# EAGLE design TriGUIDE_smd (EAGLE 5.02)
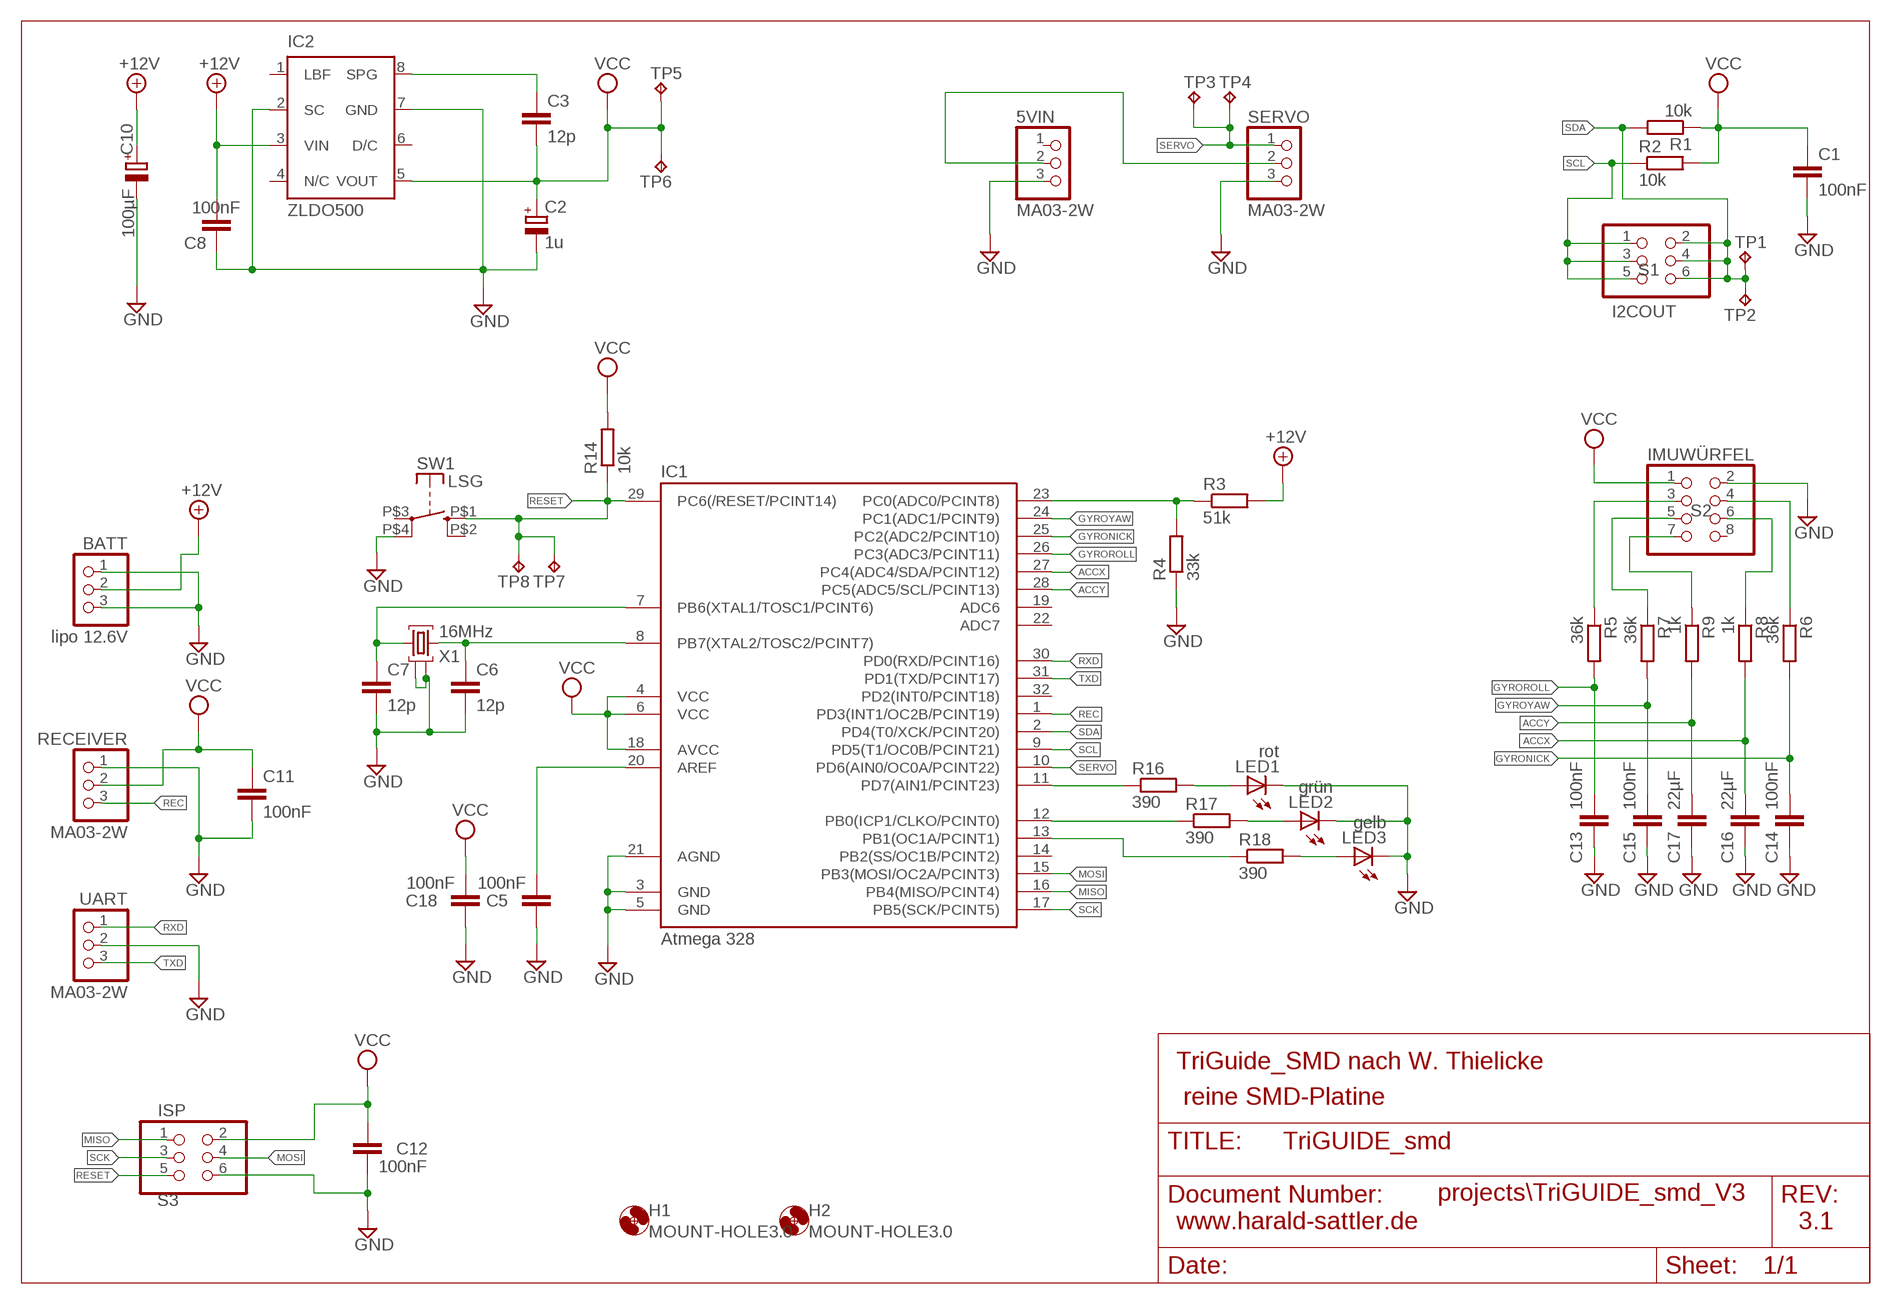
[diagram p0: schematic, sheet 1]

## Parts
5VIN  MA03-2W  PINHD-1X3_2.54-SMD  [1X03SMD]
BATT  lipo 12.6V  PINHD-1X3_2.54-SMD  [1X03SMD]
C1  100nF  C-EUC1206  [C1206]
C2  1u  CPOL-EUSMCB  [SMC_B]
C3  12p  C-EUC1206  [C1206]
C5  100nF  C-EUC1206  [C1206]
C6  12p  C-EUC1206  [C1206]
C7  12p  C-EUC1206  [C1206]
C8  100nF  C-EUC1206  [C1206]
C10  100µF  CPOL-EUD/7343-31W  [D/7343-31W]
C11  100nF  C-EUC1206  [C1206]
C12  100nF  C-EUC1206  [C1206]
C13  100nF  C-EUC1206  [C1206]
C14  100nF  C-EUC1206  [C1206]
C15  100nF  C-EUC1206  [C1206]
C16  22µF  C-EUC1206  [C1206]
C17  22µF  C-EUC1206  [C1206]
C18  100nF  C-EUC1206  [C1206]
H1  MOUNT-HOLE3.0  [3,0]
H2  MOUNT-HOLE3.0  [3,0]
I2COUT  S1  PINHD-2X3_2.54-SMD  [2X03SMD]
IC1  Atmega 328  MEGA48/88/168-AU  [TQFP32-08]
IC2  ZLDO500  [SM8]
IMUWÜRFEL  S2  PINHD-2X4_2.54-SMD  [2X04SMD]
ISP  S3  PINHD-2X3_2.54-SMD  [2X03SMD]
LED1  rot  LEDCHIPLED_1206  [CHIPLED_1206]
LED2  grün  LEDCHIPLED_1206  [CHIPLED_1206]
LED3  gelb  LEDCHIPLED_1206  [CHIPLED_1206]
R1  10k  R-EU_R1206  [R1206]
R2  10k  R-EU_R1206  [R1206]
R3  51k  R-EU_R1206  [R1206]
R4  33k  R-EU_R1206  [R1206]
R5  36k  R-EU_R1206  [R1206]
R6  36k  R-EU_R1206  [R1206]
R7  36k  R-EU_R1206  [R1206]
R8  1k  R-EU_R1206  [R1206]
R9  1k  R-EU_R1206  [R1206]
R14  10k  R-EU_R1206  [R1206]
R16  390  R-EU_R1206  [R1206]
R17  390  R-EU_R1206  [R1206]
R18  390  R-EU_R1206  [R1206]
RECEIVER  MA03-2W  PINHD-1X3_2.54-SMD  [1X03SMD]
SERVO  MA03-2W  PINHD-1X3_2.54-SMD  [1X03SMD]
SW1  LSG  [LSG]
TP1  TPB1,27  [B1,27]
TP2  TPB1,27  [B1,27]
TP3  TPB1,27  [B1,27]
TP4  TPB1,27  [B1,27]
TP5  TPB1,27  [B1,27]
TP6  TPB1,27  [B1,27]
TP7  TPB1,27  [B1,27]
TP8  TPB1,27  [B1,27]
UART  MA03-2W  PINHD-1X3_2.54-SMD  [1X03SMD]
X1  16MHz  X22  [X22]

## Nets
+12V: BATT.2 C8.2 C10.+ IC2.3(VIN) R3.2
ACCX: C16.1 IC1.27(PC4(ADC4/SDA/PCINT12)) R8.2
ACCY: C17.2 IC1.28(PC5(ADC5/SCL/PCINT13)) R9.2
AREF: C5.2 IC1.20(AREF)
GND: 5VIN.3 BATT.1 BATT.3 C1.2 C2.- C5.1 C6.2 C7.2 C8.1 C10.- C11.2 C12.2 C13.2 C14.1 C15.1 C16.2 C17.1 C18.1 IC1.3(GND) IC1.5(GND) IC1.21(AGND) IC2.2(SC) IC2.7(GND) IMUWÜRFEL.2 ISP.6 LED1.C LED2.C LED3.C R4.1 RECEIVER.1 SERVO.3 SW1.P$4(P) UART.2 X1.P$2 X1.P$4
GYRONICK: C14.2 IC1.25(PC2(ADC2/PCINT10)) R6.2
GYROROLL: C13.1 IC1.26(PC3(ADC3/PCINT11)) R5.2
GYROYAW: C15.2 IC1.24(PC1(ADC1/PCINT9)) R7.2
LED1: IC1.11(PD7(AIN1/PCINT23)) R16.1
LED2: IC1.12(PB0(ICP1/CLKO/PCINT0)) R17.1
LED3: IC1.13(PB1(OC1A/PCINT1)) R18.1
MISO: IC1.16(PB4(MISO/PCINT4)) ISP.1
MOSI: IC1.15(PB3(MOSI/OC2A/PCINT3)) ISP.4
N$1: C3.1 IC2.8(SPG)
N$4: 5VIN.2 SERVO.2
N$5: IMUWÜRFEL.3 R5.1
N$8: LED1.A R16.2
N$9: LED2.A R17.2
N$10: LED3.A R18.2
N$14: IC1.23(PC0(ADC0/PCINT8)) R3.1 R4.2
N$16: IMUWÜRFEL.4 R6.1
N$18: IMUWÜRFEL.5 R7.1
N$19: IMUWÜRFEL.6 R8.1
N$20: IMUWÜRFEL.7 R9.1
REC: IC1.1(PD3(INT1/OC2B/PCINT19)) RECEIVER.3
RESET: IC1.29(PC6(/RESET/PCINT14)) ISP.5 R14.1 SW1.P$1(S) TP7.PP(TP) TP8.PP(TP)
RXD: IC1.30(PD0(RXD/PCINT16)) UART.1
SCK: IC1.17(PB5(SCK/PCINT5)) ISP.3
SCL: I2COUT.1 I2COUT.3 I2COUT.5 IC1.9(PD5(T1/OC0B/PCINT21)) R2.1
SDA: I2COUT.2 I2COUT.4 I2COUT.6 IC1.2(PD4(T0/XCK/PCINT20)) R1.2 TP1.PP(TP) TP2.PP(TP)
SERVO: IC1.10(PD6(AIN0/OC0A/PCINT22)) SERVO.1 TP3.PP(TP) TP4.PP(TP)
TXD: IC1.31(PD1(TXD/PCINT17)) UART.3
VCC: C1.1 C2.+ C3.2 C11.1 C12.1 C18.2 IC1.4(VCC) IC1.6(VCC) IC1.18(AVCC) IC2.5(VOUT) IMUWÜRFEL.1 ISP.2 R1.1 R2.2 R14.2 RECEIVER.2 TP5.PP(TP) TP6.PP(TP)
XTAL1: C7.1 IC1.7(PB6(XTAL1/TOSC1/PCINT6)) X1.P$1
XTAL2: C6.1 IC1.8(PB7(XTAL2/TOSC2/PCINT7)) X1.P$3
Unconnected: 5VIN.1 IC1.14(PB2(SS/OC1B/PCINT2)) IC1.19(ADC6) IC1.22(ADC7) IC1.32(PD2(INT0/PCINT18)) IC2.1(LBF) IC2.4(N/C) IC2.6(D/C) IMUWÜRFEL.8 SW1.P$2(S) SW1.P$3(P)

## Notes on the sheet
- TriGuide_SMD nach W. Thielicke
- reine SMD-Platine
- projects\\TriGUIDE_smd_V3
- www.harald-sattler.de | 3.1

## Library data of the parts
5VIN BATT RECEIVER SERVO UART = pinhead:PINHD-1X3: PIN HEADER
C1 C3 C5-C8 C11-C18 = rcl:C-EU: CAPACITOR, European symbol
C2 C10 = rcl:CPOL-EU: POLARIZED CAPACITOR, European symbol
H1 H2 = holes:MOUNT-HOLE: MOUNTING HOLE with drill center marker
I2COUT ISP = pinhead:PINHD-2X3: PIN HEADER
IC1 = avr-4:MEGA48/88/168
IC2 = zetex:ZLDO500
IMUWÜRFEL = pinhead:PINHD-2X4: PIN HEADER
LED1-LED3 = led:LED: LED
R1-R9 R14 = resistor:R-EU_: RESISTOR, European symbol
R16-R18 = rcl:R-EU_: RESISTOR, European symbol
SW1 = Schurter:LSG
TP1-TP8 = testpad:TP: Test pad
X1 = crystal:X22: Reichelt SMD Keramik Quarz EUROQUARTZ X22, Standard SMD-Quarz Keramikgehäuse 2x2,5x0,6mm Grundton-Modus Lastkapazität: 12pF

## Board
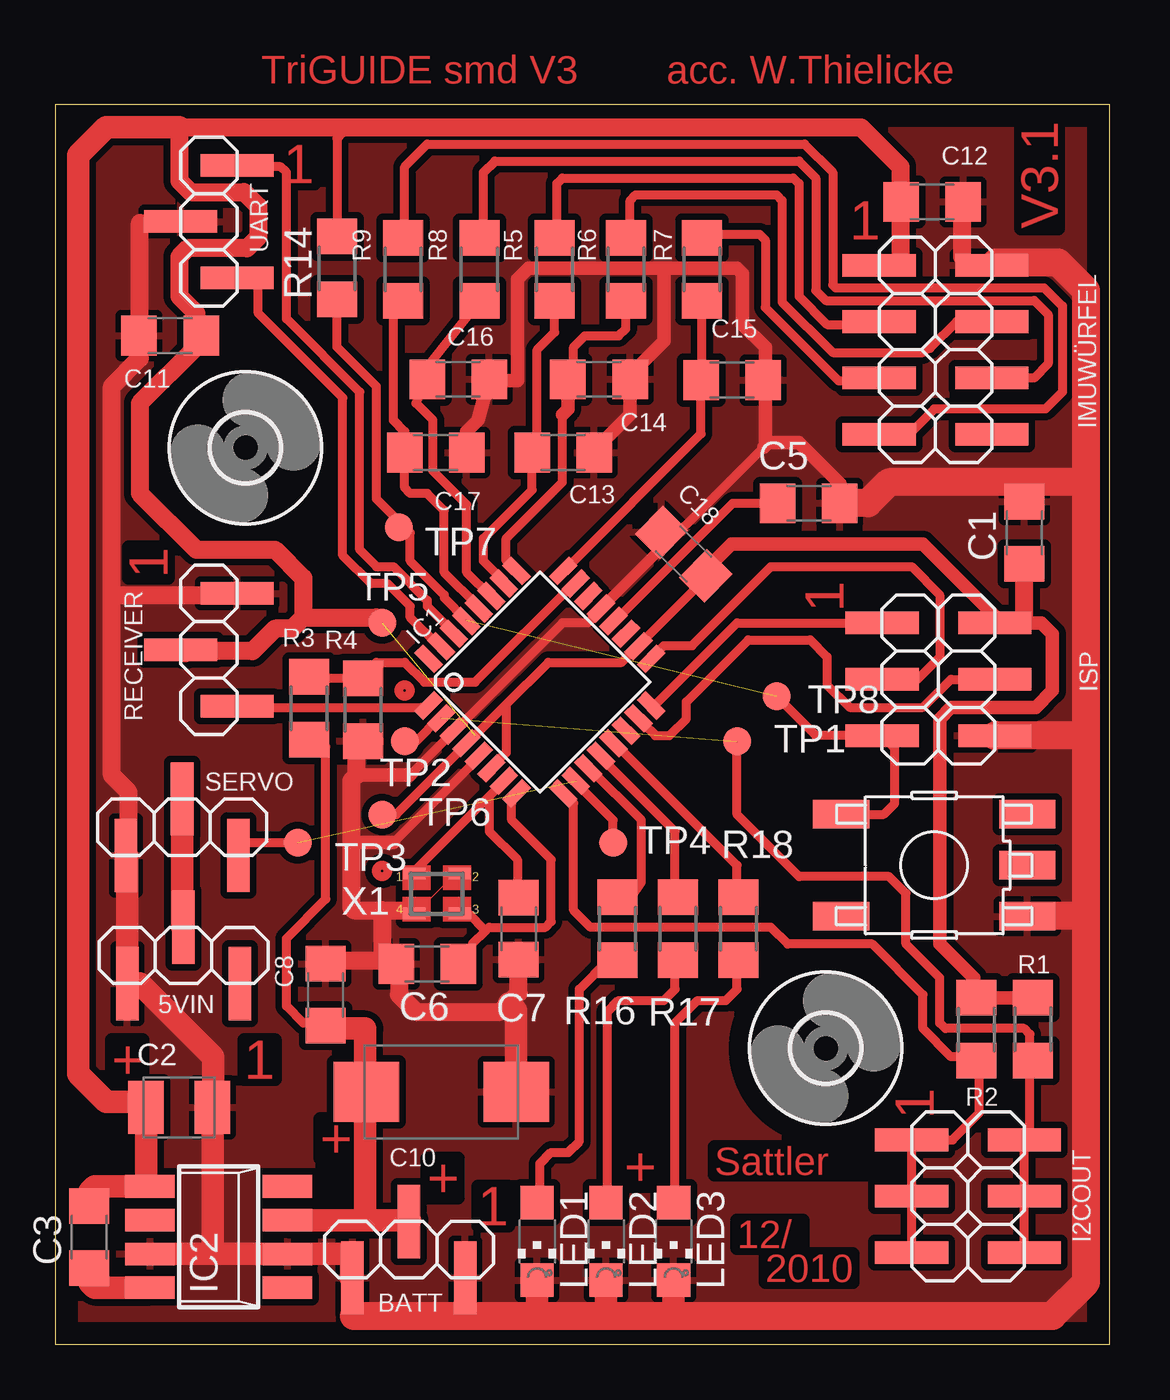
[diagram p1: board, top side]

Size 47.55 x 55.88 mm. Coordinates in mm from the lower left corner, seen from the top.
Outline: 0,0 47.55,0 47.55,55.88 0,55.88 0,0
Copper layers (1*16): Top 0.035mm / dielectric 1.5mm / Bottom 0.035mm
Design rules "bilex": minimum track width 0.25mm, minimum drill 0.6mm, track to track 12mil, track to pad 12mil, pad to pad 12mil, via to via 12mil, smd to smd 12mil, copper to edge 40mil, drill to drill 8mil, minimum pad ring 10mil, minimum via ring 8mil, stop-mask expansion 4mil, vias tented up to drill 0mil, thermal gap 10mil

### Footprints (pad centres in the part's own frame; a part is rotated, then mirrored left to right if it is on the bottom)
1X03SMD = smd 1.016 x 3.302: 1 -1.27,1.27; 2 1.27,-1.27; 3 3.81,1.27
C1206 = smd 1.6 x 1.8: 1 -1.4,0; 2 1.4,0
SMC_B = smd 1.6 x 2.4: + -1.5,0; - 1.5,0
D/7343-31W = smd 2.95 x 2.7: + 3.375,0; - -3.375,0
3,0 = hole 3: 0,0
2X03SMD = smd 1.016 x 3.302: 1 -1.27,-3.81; 2 -1.27,1.27; 3 1.27,-3.81; 4 1.27,1.27; 5 3.81,-3.81; 6 3.81,1.27
TQFP32-08 = smd 1.27 x 0.559: 1 -4.293,2.8; 2 -4.293,2; 3 -4.293,1.2; 4 -4.293,0.4; 5 -4.293,-0.4; 6 -4.293,-1.2; 7 -4.293,-2; 8 -4.293,-2.8; 17 4.293,-2.8; 18 4.293,-2; 19 4.293,-1.2; 20 4.293,-0.4; 21 4.293,0.4; 22 4.293,1.2; 23 4.293,2; 24 4.293,2.8 | smd 0.559 x 1.27: 9 -2.8,-4.293; 10 -2,-4.293; 11 -1.2,-4.293; 12 -0.4,-4.293; 13 0.4,-4.293; 14 1.2,-4.293; 15 2,-4.293; 16 2.8,-4.293; 25 2.8,4.293; 26 2,4.293; 27 1.2,4.293; 28 0.4,4.293; 29 -0.4,4.293; 30 -1.2,4.293; 31 -2,4.293; 32 -2.8,4.293
SM8 = smd 1.016 x 2.235: 1 -2.286,-3.099; 2 -0.762,-3.099; 3 0.762,-3.099; 4 2.286,-3.099; 5 2.286,3.099; 6 0.762,3.099; 7 -0.762,3.099; 8 -2.286,3.099
2X04SMD = smd 1.016 x 3.302: 1 -1.27,-3.81; 2 -1.27,1.27; 3 1.27,-3.81; 4 1.27,1.27; 5 3.81,-3.81; 6 3.81,1.27; 7 6.35,-3.81; 8 6.35,1.27
CHIPLED_1206 = smd 1.5 x 1.5: A 0,-1.75; C 0,1.75
R1206 = smd 1.6 x 1.803: 1 -1.422,0; 2 1.422,0
LSG = smd 2.54 x 1.27: P$1 -4.2,2.3; P$2 4.2,2.3; P$3 -4.2,-2.3; P$4 4.2,-2.3; P$5 4.2,0
B1,27 = smd 1.27 x 1.27: PP 0,0
X22 = smd 1.016 x 0.508: P$1 -1.524,0.254; P$2 0.508,0.254; P$3 0.508,-1.524; P$4 -1.524,-1.524

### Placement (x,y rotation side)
5VIN  7.05,17.53 180 top
BATT  17.21,4.25 180 top
C1  43.69,36.58 90 top
C2  5.59,10.67 0 top
C3  1.52,4.83 90 top
C5  33.97,37.91 180 top
C6  16.76,17.14 180 top
C7  20.89,18.73 270 top
C8  12.19,15.75 270 top
C10  17.4,11.37 180 top
C11  5.18,45.47 180 top
C12  39.53,51.5 0 top
C13  22.89,40.2 0 top
C14  24.51,43.5 180 top
C15  30.51,43.47 180 top
C16  18.16,43.5 0 top
C17  17.14,40.2 180 top
C18  28.32,35.62 315.4 top
H1  34.73,13.34 0 top
H2  8.57,40.42 0 top
I2COUT  42.42,7.94 270 top
IC1  21.84,29.84 45 top
IC2  7.37,4.83 90 top
IMUWÜRFEL  40.96,47.37 270 top
ISP  41.08,31.24 270 top
LED1  21.72,4.64 180 top
LED2  24.83,4.64 180 top
LED3  27.88,4.64 180 top
R1  44.07,14.19 270 top
R2  41.53,14.19 90 top
R3  11.43,28.67 270 top
R4  13.87,28.61 90 top
R5  22.51,48.45 270 top
R6  25.72,48.45 270 top
R7  29.15,48.45 270 top
R8  19.11,48.45 270 top
R9  15.68,48.45 270 top
R14  12.7,48.51 90 top
R16  25.34,18.73 270 top
R17  28.07,18.73 270 top
R18  30.8,18.73 270 top
RECEIVER  6.92,32.58 270 top
SERVO  6.99,23.3 180 top
SW1  39.62,21.59 0 top
TP1  30.73,27.18 0 top
TP2  15.75,27.18 0 top
TP3  10.92,22.61 0 top
TP4  25.15,22.61 0 top
TP5  14.73,32.51 0 top
TP6  14.73,23.88 0 top
TP7  15.49,36.83 0 top
TP8  32.51,29.21 0 top
UART  6.92,51.88 270 top
X1  17.72,20.95 0 top

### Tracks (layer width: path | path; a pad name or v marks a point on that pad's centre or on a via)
+12V
  Top 0.406: 11.94,14.48 11.18,14.48 10.41,15.24 10.41,18.29 12.19,20.07 12.19,26.92 11.43,27.18 R3.2
  Top 0.813: 12.19,14.22 11.94,14.48 | R3.2
  Top 1.016: 12.19,14.22 13.97,14.22 13.97,11.43 13.97,5.59 | BATT.2 16,5.59 13.97,5.59 | IC2.3 13.97,5.59
  Top 1.27: 13.97,11.43 C10.+ | 12.19,14.22 C8.2
ACCX
  Top 0.254: C16.1 16.25,43.44 16.26,43.43 16.32,43.5 | IC1.27 19.61,33.73
  Top 0.406: 16.32,43.5 R8.2 | C16.1 16.25,42.42 17.02,41.66 17.02,39.37 18.54,37.85 18.54,34.8 19.61,33.73
ACCY
  Top 0.254: 19.05,33.27 19.09,33.06 IC1.28
  Top 0.406: 19.05,33.27 17.53,34.8 17.53,37.59 16.76,38.35 16,38.35 15.74,38.61 C17.2 15.74,41.15 15.24,41.66 15.24,46.48 15.75,46.99 15.71,47.03 R9.2
AREF
  Top 0.406: IC1.20 25.23,32.6 30.54,37.91 C5.2
GND
  Top 0: 16.26,19.56 16.51,19.81 16.64,19.81 18.03,21.21 X1.P$2 18.29,21.21
  Top 0.25: IC1.5 18.8,26.16 | 17.78,27.43 IC1.3 18.29,27.94 | 40.89,50.8 C12.2 | 40.89,49.02 IMUWÜRFEL.2 43.69,48.51 | 24.26,32.77 IC1.21 24.89,33.4
  Top 0.254: 24.29,40.29 C13.2 | 25.91,43.43 25.91,43.44 C14.1 | 32,43.43 31.97,43.47 C15.1 | 19.05,43.43 19.05,43.44 C16.2 | 18.54,40.39 18.55,40.38 C17.1 | 15.24,17.27 15.24,17.02 | 16.26,19.49 X1.P$4
  Top 0.305: 16.26,19.49 16.26,19.56 16,19.56
  Top 0.406: 18.29,27.94 22.86,32.51 24,32.51 24.26,32.77 | 31.94,40.45 24.89,33.4 24.89,33.53 27.69,36.32 27.4,36.61 C18.1 | IC1.5 19.09,26.46 15.24,22.61 | 17.78,27.43 16,25.65 | 31.78,43.47 31.75,43.43 | C15.1 31.78,43.47 | 31.78,43.47 32,43.69
  Top 0.61: 27.43,48.51 21.34,48.51 20.83,48.01 20.83,43.43 19.05,43.43 | 24.29,40.29 25.91,41.91 25.91,43.43 | C14.1 25.91,43.69 27.43,45.21 27.43,48.51 | 31.94,40.45 32,40.51 32,40.64 | 32,40.64 32,43.43 | C16.2 19.05,41.66 18.54,41.15 18.54,40.39 | 13.34,22.61 15.24,22.61 | 16,25.65 13.59,25.65 | C5.1 35.37,38.8 33.53,40.64 32,40.64 | 27.43,48.51 30.73,48.51 30.99,48.26 30.99,45.97 32,44.96 32,43.69
  Top 0.813: 40.89,49.02 40.89,50.8 | 14.73,19.56 13.46,19.56 13.34,19.68 13.34,22.61 13.34,25.4 13.59,25.65 13.59,26.54 13.96,27.18 R4.1 | C6.2 15.24,17.27 14.73,17.78 14.73,19.56 | 14.73,19.56 16,19.56 | 42.42,48.77 42.29,48.64 IMUWÜRFEL.2 | C7.2 20.89,15.81 20.45,15.37 20.07,14.99 16.26,14.99 15.49,15.75 15.49,16.76 15.24,17.02 C6.2 | 15.49,17.27 | C6.2 15.49,17.27 | UART.2 5.59,50.55 3.81,50.55 3.81,45.47 | 36.64,37.91 36.58,37.85 | 43.84,19.3 SW1.P$4 | 43.69,38.86 C1.2 | C8.1 12.19,17.02 12.45,17.27 15.49,17.27 | 3.81,45.47 C11.2 | 3.81,45.47 3.81,44.45 2.54,43.18 2.54,33.78 | RECEIVER.1 8.13,33.78 2.54,33.78 | 2.54,33.78 2.54,25.65 3.3,24.89 3.3,21.84 3.17,21.97 SERVO.3
  Top 1.016: C10.- 20.77,15.04 20.45,15.37 | SERVO.3 3.17,22.1 3.24,22.04 5VIN.3 3.81,16.26 7.11,12.95 7.11,10.41 7.09,10.44 C2.- 7.09,4.09 7.11,4.06 | IC2.7 7.11,4.06 | 7.11,4.06 IC2.2 13.34,4.06 13.34,2.92 BATT.3 13.4,1.59 13.46,1.52 13.46,1.27 | BATT.1 18.48,1.33 18.54,1.27 | LED1.C 21.72,1.4 21.84,1.27 | LED2.C 24.83,1.33 24.89,1.27 | LED3.C 27.88,1.33 27.94,1.27
  Top 1.27: 46.48,38.86 46.48,47.5 45.21,48.77 42.42,48.77 | C5.1 36.64,37.91 37.59,38.86 43.69,38.86 46.48,38.86 | 46.48,19.3 46.48,2.79 44.96,1.27 27.94,1.27 24.89,1.27 21.84,1.27 18.54,1.27 13.46,1.27 | 46.48,19.3 46.48,27.43 | 46.48,27.43 46.48,38.86 | 46.48,19.3 43.84,19.3 | 46.48,27.43 ISP.6
  pour Top (isolate 0.305): 0,55.88 47.62,55.88 47.62,0 0,0
GYRONICK
  Top 0.254: 20.83,34.8 20.79,34.84 IC1.25
  Top 0.305: 20.79,34.84 20.32,35.31
  Top 0.406: 22.86,41.91 22.86,38.86 20.32,36.32 20.32,35.31 | R6.2 25.72,45.78 25.4,45.47 23.88,45.47 23.37,44.96 23.37,43.69 23.11,43.43 23.11,43.44 C14.2
  Top 0.61: C14.2 23.11,42.16 22.86,41.91
GYROROLL
  Top 0.254: 20.32,34.29 IC1.26
  Top 0.406: 20.32,34.29 19.3,35.31 19.3,36.32 21.49,38.51 C13.1 21.49,40.29 21.72,40.51 21.72,44.83 22.51,45.62 R5.2
GYROYAW
  Top 0.254: 22.86,34.8 22.9,34.84 IC1.24
  Top 0.406: 22.9,34.84 29.11,41.05 C15.2 29.18,43.47 | 29.18,43.47 29.21,43.43 | R7.2 29.15,43.5 29.18,43.47
LED1
  Top 0.406: IC1.11 24.08,25.96 26.42,23.62 26.42,20.83 25.91,20.07 25.4,20.07 25.34,20.13 R16.1
LED2
  Top 0.25: 24.89,26.16 IC1.12
  Top 0.406: R17.1 27.98,20.07 27.94,20.07 27.94,23.11 24.89,26.16
LED3
  Top 0.25: 25.4,26.92 IC1.13
  Top 0.406: 30.73,20.09 30.73,20.07 | R18.1 30.73,20.09 | 25.4,26.92 30.73,21.59 30.73,20.09
MISO
  Top 0.406: IC1.16 26.86,28.77 26.92,28.7 30.73,32.51 ISP.1 37.34,32.51
MOSI
  Top 0.25: 26.54,27.94 IC1.15
  Top 0.406: 26.54,27.94 27.05,27.43 27.69,27.43 28.45,28.19 28.45,28.96 31.24,31.75 34.04,31.75 34.8,30.99 34.8,29.72 35.81,28.7 39.12,28.7 40.39,29.97 ISP.4
N$1
  Top 1.016: C3.1 1.52,2.79 1.78,2.54 IC2.8
N$4
  Top 1.016: 5VIN.2 5.71,18.8 SERVO.2
N$5
  Top 0.254: 37.34,46.23 37.21,46.1 IMUWÜRFEL.3
  Top 0.305: 37.08,45.97 37.15,46.04 IMUWÜRFEL.3
  Top 0.406: 37.08,45.97 34.8,45.97 33.53,47.24 33.53,52.32 33.27,52.58 22.86,52.58 22.61,52.32 22.61,49.78 R5.1
N$8
  Top 0.406: R16.2 25.36,17.31 25.4,17.27 24.89,17.27 23.62,16 23.62,9.14 23.11,8.64 22.35,8.64 21.84,8.13 21.84,6.35 21.88,6.39 LED1.A
N$9
  Top 0.406: R17.2 27.98,17.31 27.94,17.27 27.94,16 27.43,15.49 25.4,15.49 24.89,14.99 24.89,6.6 25.11,6.64 LED2.A
N$10
  Top 0.406: R18.2 30.95,17.31 30.99,17.27 30.73,17.02 30.73,16 30.23,15.49 28.96,15.49 27.94,14.48 27.94,6.35 27.9,6.39 LED3.A
N$14
  Top 0.254: 23.37,34.29 IC1.23
  Top 0.305: R4.2 14.17,30.03 14.35,29.84 | 11.43,29.97 | R3.1 11.43,29.97 | 11.43,29.97 11.49,30.03
  Top 0.406: 23.37,34.29 18.92,29.84 16.64,29.84 15.75,30.73 14.48,30.73 13.88,30.13 R4.2 11.49,30.03
N$16
  Top 0.305: 40.64,46.1 IMUWÜRFEL.4 | 39.37,44.83 39.43,44.9 39.37,44.96
  Top 0.406: 39.43,44.9 40.64,46.1 | 39.37,44.96 39.12,44.7 35.05,44.7 32.77,46.99 32.77,51.56 32.51,51.82 26.16,51.82 25.91,51.56 25.91,50.04 25.72,49.85 | 25.72,49.85 25.65,49.78 | R6.1 25.72,49.85
N$18
  Top 0.305: 37.34,43.43 37.21,43.56 IMUWÜRFEL.5
  Top 0.406: 37.34,43.43 35.31,43.43 32,46.74 32,49.78 31.75,50.04 29.46,50.04 29.21,49.78 29.15,49.85 R7.1
N$19
  Top 0.406: IMUWÜRFEL.6 44.13,43.56 44.77,44.2 44.77,46.42 44.13,47.05 34.73,47.05 34.29,47.5 34.29,52.58 33.53,53.34 19.81,53.34 19.3,52.83 19.3,50.29 19.05,50.04 19.11,49.97 R8.1
N$20
  Top 0.25: 38.61,41.15 IMUWÜRFEL.7
  Top 0.254: 45.4,46.8 45.4,46.74
  Top 0.406: 45.4,46.74 45.4,42.93 44.64,42.16 39.62,42.16 38.61,41.15 | 45.4,46.8 44.58,47.62 35.18,47.62 35.05,47.75 35.05,52.83 33.78,54.1 16.76,54.1 15.75,53.09 15.75,50.04 15.68,49.97 R9.1
REC
  Top 0.25: 16.51,28.7 IC1.1 | RECEIVER.3 9.65,28.7
  Top 0.406: 9.65,28.7 16.51,28.7
RESET  (1 unrouted)
  Top 0.305: IC1.29 18.53,32.66 | 17.53,33.66 17.53,33.78
  Top 0.406: 18.53,32.66 17.53,33.66 | 17.53,33.78 16,35.31 16,36.58 15.75,36.83 TP7.PP 15.49,37.08 14.48,38.1 14.48,43.18 12.7,44.96 R14.1 | SW1.P$1 37.35,23.89 37.85,24.38 37.85,26.86 ISP.5 34.29,27.43 TP8.PP
RXD
  Top 0.254: IC1.30 17.96,32.08
  Top 0.305: 18.03,32 18.01,32.03 IC1.30 | 8.26,53.09 UART.1
  Top 0.406: 18.01,32.03 16.76,33.27 16.76,33.53 15.24,35.05 14.48,35.05 13.72,35.81 13.72,42.93 10.41,46.23 10.41,52.83 10.16,53.09 8.26,53.09
SCK
  Top 0.25: IC1.17 27.18,30.99
  Top 0.406: 37.08,29.97 ISP.3 38.86,29.97 39.88,30.99 39.88,33.78 38.61,35.05 32.26,35.05 28.7,31.5 27.43,31.5 26.86,30.92 IC1.17
SCL
  Top 0.406: IC1.9 22.92,24.83 23.37,24.38 23.37,19.56 24.13,18.8 32.26,18.8 33.02,18.03 36.83,18.03 39.12,15.75 39.12,14.22 40.39,12.95 41.15,12.95 41.4,12.7 41.47,12.77 R2.1 41.59,12.77 41.66,12.7 41.66,10.41 40.45,9.21 I2COUT.1 I2COUT.3 I2COUT.5 38.61,4.06
SDA  (1 unrouted)
  Top 0.406: IC1.2 17.3,28.22 16.26,27.18 TP2.PP | TP1.PP 30.73,23.88 33.53,21.08 37.59,21.08 38.35,20.32 38.35,18.03 39.88,16.51 39.88,14.48 40.13,14.22 43.69,14.22 43.94,13.97 43.94,13.21 44.2,12.95 44.07,12.83 R1.2 44.01,12.77 43.94,12.7 43.94,9.4 43.75,9.21 I2COUT.2 I2COUT.4 I2COUT.6
SERVO  (1 unrouted)
  Top 0.406: IC1.10 23.46,25.3 25.15,23.62 TP4.PP | 8.38,22.61 TP3.PP
  Top 0.813: SERVO.1 8.26,22.48 8.38,22.61
TXD
  Top 0.254: IC1.31 17.39,31.63
  Top 0.305: 17.53,31.5 17.5,31.47 IC1.31 17.3,31.47 | 8.13,48.01 UART.3
  Top 0.406: 17.3,31.47 16,32.77 16,33.27 14.99,34.29 14.22,34.29 12.95,35.56 12.95,42.67 9.14,46.48 9.14,48.01 8.13,48.01
VCC  (1 unrouted)
  Top 0.25: IC1.4 18.92,27.43 | 20.07,26.42 IC1.6 | C12.1 38.1,50.8
  Top 0.254: 38.1,51.31 38.13,51.34 C12.1 | IMUWÜRFEL.1 37.21,48.64 37.34,48.51 37.85,49.02 38.1,49.02
  Top 0.406: 20.32,28.83 22.23,30.73 25.53,30.73 26.29,31.5 26.29,31.49 IC1.18 26.39,31.59 29.46,34.67 29.24,34.77 C18.2 | 18.92,27.43 20.32,28.83 | 20.07,26.42 20.32,26.67 20.32,28.83 | IC1.4 18.53,27.04 15.37,23.88 TP6.PP | ISP.2 42.42,32.51 42.42,32.77 | 14.48,32.77 TP5.PP | 12.95,54.86 12.95,54.61 12.7,54.36 R14.2
  Top 0.61: ISP.2 43.69,32.51 44.45,32.51 44.96,32 44.96,29.46 44.2,28.7 40.39,28.7 39.88,28.19 39.88,18.03 41.4,16.51 41.4,15.75 R2.2 | 29.19,34.4 C18.2 29.19,34.78 30.48,36.07 39.12,36.07 42.42,32.77 | R2.2 41.66,15.49 | R2.2 R1.1 | R1.1 | R1.1 44.2,15.49
  Top 0.813: 38.1,50.8 38.1,49.02 | C12.1 38.13,51.53 38.1,51.56 38.1,53.09 36.32,54.86 12.95,54.86 5.59,54.86 5.59,52.45 6.1,51.94 8.51,51.94 9.14,51.31 9.14,49.91 8.64,49.4 5.97,49.4 5.59,49.02 5.59,47.24 6.35,46.48 6.35,45.72 6.6,45.47 | 11.18,32.77 11.18,34.54 9.91,35.81 6.35,35.81 3.81,38.35 3.81,42.42 6.35,44.96 6.35,45.21 6.6,45.47 | 11.18,32.77 10.67,32.26 9.91,32.26 8.89,31.24 5.84,31.24 | 11.18,32.77 14.48,32.77 | 43.69,32.51 C1.1 | RECEIVER.2 5.59,31.24 | 6.6,45.47 C11.1
  Top 1.016: 5.84,31.24 5.78,31.3 RECEIVER.2 | 5.59,54.86 2.29,54.86 1.02,53.59 1.02,12.19 2.29,10.92 4.06,10.92 4.09,10.9 C2.+ 4.09,7.14 4.06,7.11 | C3.2 1.52,6.86 1.78,7.11 4.06,7.11 | 4.06,7.11 IC2.5
XTAL1
  Top 0.25: 19.56,24.64 20.07,25.15 IC1.7 | 20.83,20.07 C7.1
  Top 0.305: X1.P$1 16.19,21.34 | 20.26,25.4 20.25,25.39 IC1.7
  Top 0.406: 19.56,24.64 19.56,23.11 20.83,21.84 20.83,20.07 | 16.19,21.34 20.25,25.39
XTAL2
  Top 0.25: 19.4,18.64 19.56,18.8 | 20.57,24.38 IC1.8 | C6.1 18.8,18.03
  Top 0.305: 18.61,19.43 X1.P$3 | 19.4,18.64
  Top 0.406: 20.57,24.38 20.57,23.62 22.35,21.84 22.35,19.05 22.1,18.8 19.56,18.8 | 18.8,18.03 19.4,18.64 18.61,19.43
(copper drawn outside any net)
  shapes: Top circle x2

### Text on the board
Top: TriGUIDE smd V3 | acc. W.Thielicke | 1 | 1 | V3.1 | 1 | 1 | 1 | + | 1 | + | Sattler | + | + | 1 | 12/ | 2010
